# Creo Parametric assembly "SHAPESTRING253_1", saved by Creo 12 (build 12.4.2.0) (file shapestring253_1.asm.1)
Units: Custom; MM, KILOGRAM, SECS

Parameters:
  PTC_WM_ITERATION = "0"
  PTC_WM_VERSION = "-.0"
  PTC_WM_LIFECYCLE_STATE = "In Work"
  PTC_WM_LIFECYCLE = "MO_CADDocument"
  PTC_WM_CREATED_BY = "Maximilian Roepper (Z0017RMS: MO)"
  PTC_WM_CREATED_ON = "18-Sep-26 11:36:42 AM"
  PTC_WM_MODIFIED_BY = "Maximilian Roepper (Z0017RMS: MO)"
  PTC_WM_MODIFIED_ON = "18-Sep-26 11:36:46 AM"
  PDMLINKNUMBER = "PDM000071455064"
  PTC_WM_NUMBER = "PDM000071455064"

Other parameters: WEIGHT, WEIGHT_FACTOR, WEIGHT_ADD, MC_ERRORS, SUPPLIER

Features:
  1. coordinate system
  2. imported feature
  3. component "SHAPESTRING066_1"
  4. component "SHAPESTRING247_1"
  5. component "SHAPESTRING248_1"
  6. component "SHAPESTRING249_1"
  7. component "SHAPESTRING250_1"
  8. component "SHAPESTRING251_1"
  9. component "SHAPESTRING252_1"

Other named items: DRW_VIEW_ORG, ROUGH-GROB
